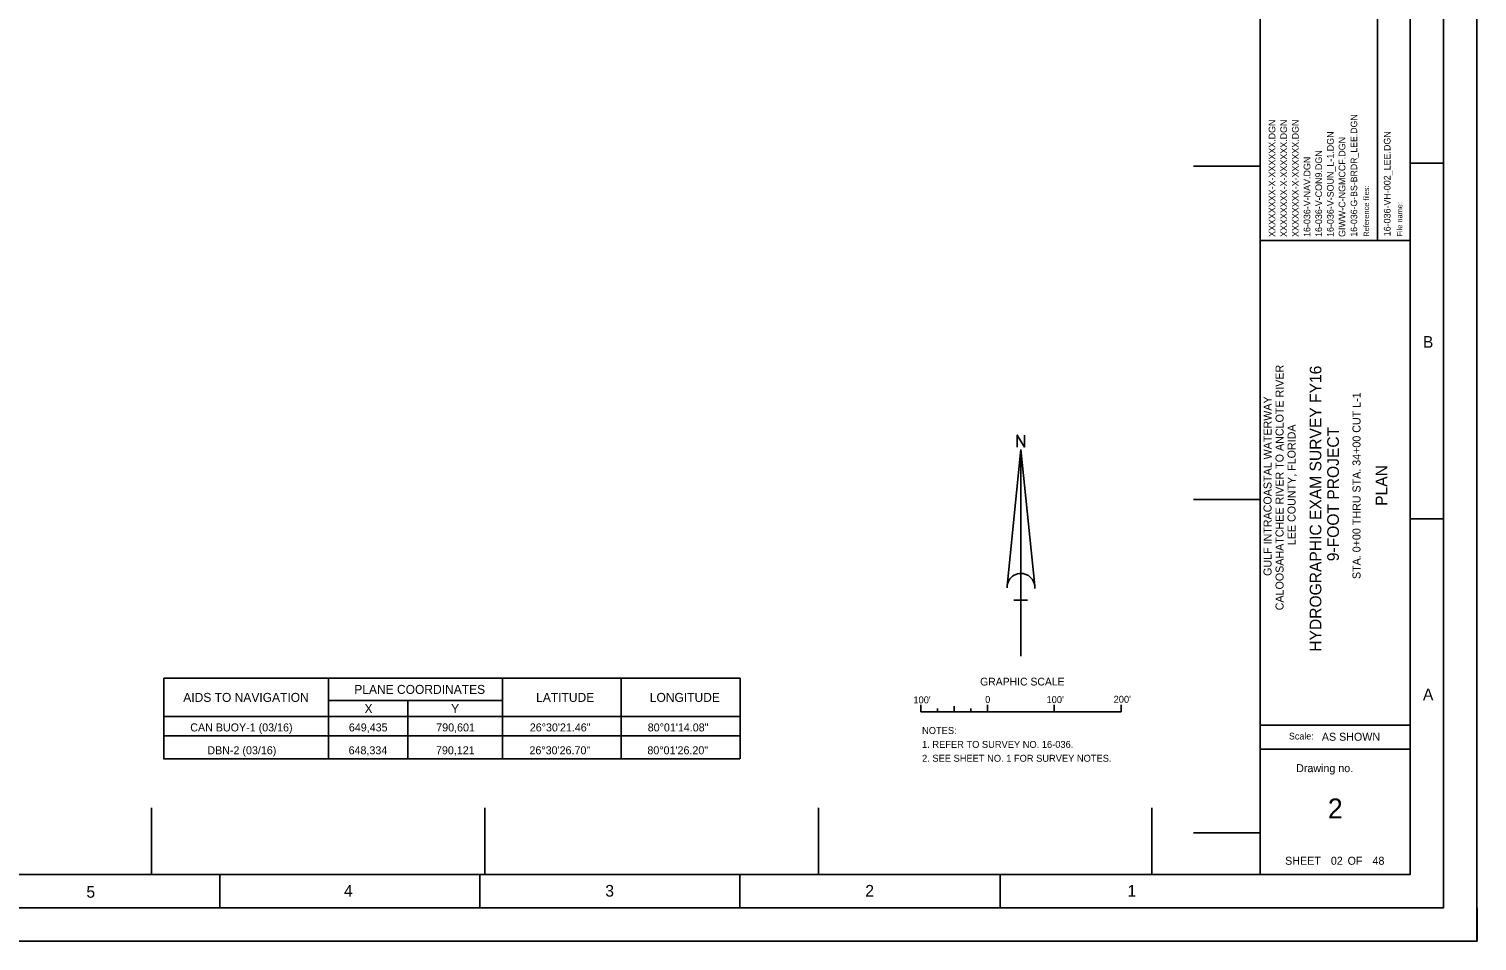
# Model space of a CAD drawing. Extents: x 647087 to 651487, y 788838 to 792238.
# Drawn here: x 649316 to 651487, y 788838 to 790206 of the extents above; entities that cross this region are included whole.
import ezdxf

# ---------------------------------------------------------------- set-up
doc = ezdxf.new("R2010")
doc.units = 0
for name, color, linetype in [('G-ANNO-NPLT', 7, 'Continuous'), ('G-ANNO-TEXT-DRWG', 7, 'Continuous'), ('G-ANNO-TEXT-PROJ', 7, 'Continuous'), ('G-ANNO-TEXT-TTLB', 7, 'Continuous'), ('G-ANNO-TTLB', 7, 'Continuous'), ('V-ANNO-NOTE', 7, 'Continuous'), ('V-ANNO-SCHD', 7, 'Continuous'), ('V-ANNO-SYMB', 7, 'Continuous'), ('V-TOPO-COOR-STAT', 7, 'Continuous')]:
    doc.layers.add(name, color=color, linetype=linetype)

msp = doc.modelspace()

# ---------------------------------------------------------------- linework, layer by layer
at = {"layer": 'G-ANNO-NPLT'}
msp.add_lwpolyline([(647087.3, 792237.8), (651487.3, 792237.8), (651487.3, 788837.9), (647087.3, 788837.9)], close=True, dxfattribs=at)
msp.add_lwpolyline([(651487.4, 788887.9), (651487.4, 788837.9), (651437.4, 788837.9)], dxfattribs=at)
at = {"layer": 'G-ANNO-TTLB'}
for p, q in [((651162.2, 792137.8), (651162.2, 788937.9)), ((651338, 790240), (651338, 789888.6)), ((651437.3, 790004.5), (651387.3, 790004.5)), ((651162.2, 789888.6), (651387.3, 789888.6)), ((651437.3, 789471.2), (651387.3, 789471.2)), ((651162.2, 789161.6), (651387.3, 789161.6)), ((651162.2, 789125.9), (651387.3, 789125.9)), ((649602.3, 788887.9), (649602.3, 788937.9)), ((649992.3, 788887.9), (649992.3, 788937.9)), ((650382.3, 788887.9), (650382.3, 788937.9)), ((650772.3, 788887.9), (650772.3, 788937.9))]:
    msp.add_line(p, q, dxfattribs=at)
for points in [[(647137.3, 788887.9), (651437.3, 788887.9), (651437.3, 792187.8), (647137.3, 792187.8)], [(651387.3, 792137.8), (647262.3, 792137.8), (647262.3, 788937.9), (651387.3, 788937.9)]]:
    msp.add_lwpolyline(points, close=True, dxfattribs=at)
at = {"layer": 'V-ANNO-NOTE'}
for p, q in [((650653.6, 789181.7), (650653.6, 789192.1)), ((650703.6, 789181.7), (650703.6, 789190.2)), ((650753.6, 789181.7), (650753.6, 789192.1)), ((650753.6, 789181.7), (650753.6, 789192.1)), ((650853.6, 789181.7), (650853.6, 789192.1)), ((650953.6, 789181.7), (650953.6, 789192.1)), ((650653.6, 789181.7), (650953.6, 789181.7)), ((650678.6, 789181.7), (650678.6, 789186.5)), ((650728.6, 789181.7), (650728.6, 789186.5)), ((650753.6, 789181.7), (650753.6, 789186.7))]:
    msp.add_line(p, q, dxfattribs=at)
at = {"layer": 'V-ANNO-SCHD'}
for p, q in [((649518.7, 789232.2), (650382.7, 789232.2)), ((649518.7, 789232.2), (649518.7, 789111.3)), ((649765.3, 789232.2), (649765.3, 789111.3)), ((650026, 789232.2), (650026, 789111.3)), ((650204.4, 789232.2), (650204.4, 789111.3)), ((650382.7, 789111.3), (650382.7, 789232.2)), ((649765.3, 789198.5), (650026, 789198.5)), ((649884.2, 789198.5), (649884.2, 789111.3)), ((649518.7, 789174.5), (650382.7, 789174.5)), ((649518.7, 789145.6), (650382.7, 789145.6)), ((649518.2, 789111.3), (650382.2, 789111.3))]:
    msp.add_line(p, q, dxfattribs=at)
at = {"layer": 'V-ANNO-SYMB'}
for p, q in [((650783, 789370.7), (650803.6, 789575.4)), ((650803.6, 789265.2), (650803.6, 789575.4)), ((650824.2, 789370.7), (650803.6, 789575.4)), ((650813.4, 789349), (650792.7, 789349))]:
    msp.add_line(p, q, dxfattribs=at)
msp.add_lwpolyline([(650797.9, 789578.8), (650797.9, 789596.9), (650809.1, 789578.8), (650809.1, 789596.9)], dxfattribs=at)
msp.add_arc((650803.6, 789368.6), 20.7, 355.2984, 182.0673, dxfattribs=at)
at = {"layer": 'V-TOPO-COOR-STAT'}
for p, q in [((651062.2, 790000), (651162.2, 790000)), ((651062.2, 789500), (651162.2, 789500)), ((649500, 788937.9), (649500, 789037.9)), ((650000, 788937.9), (650000, 789037.9)), ((650500, 788937.9), (650500, 789037.9)), ((651000, 788937.9), (651000, 789037.9)), ((651062.2, 789000), (651162.2, 789000))]:
    msp.add_line(p, q, dxfattribs=at)

# ---------------------------------------------------------------- texts
at = {"layer": 'G-ANNO-TEXT-DRWG'}
for s, height, p in [('XXXXXXXX-X-XXXXXX.DGN', 10, (651185, 789894)), ('XXXXXXXX-X-XXXXXX.DGN', 10, (651202.5, 789894)), ('XXXXXXXX-X-XXXXXX.DGN', 10, (651220, 789894)), ('16-036-V-SOUN_L-1.DGN', 10, (651272.5, 789894)), ('GIWW-C-NGMCCF.DGN', 10, (651290, 789894)), ('16-036-VH-002_LEE.DGN', 10, (651357.7, 789895)), ('16-036-V-NAV.DGN', 10, (651237.5, 789894)), ('16-036-V-CON9.DGN', 10, (651255, 789894)), ('STA. 0+00 THRU STA. 34+00 CUT L-1', 12, (651312.7, 789380.9)), ('PLAN', 17.5, (651352.8, 789490.6))]:
    msp.add_text(s, height=height, rotation=90, dxfattribs=at).set_placement(p)
for s, height, p in [('2', 30, (651263.7, 789021.7)), (' 02          48', 12, (651263.8, 788952.3))]:
    msp.add_text(s, height=height, dxfattribs=at).set_placement(p)
at = {"layer": 'G-ANNO-TEXT-PROJ'}
for s, height, p in [('16-036-G-BS-BRDR_LEE.DGN', 9.8, (651307.7, 789894.4)), ('CALOOSAHATCHEE RIVER TO ANCLOTE RIVER', 12, (651197.3, 789334)), ('HYDROGRAPHIC EXAM SURVEY FY16', 17.5, (651254, 789271.8)), ('GULF INTRACOASTAL WATERWAY', 12, (651179.3, 789385.6)), ('LEE COUNTY, FLORIDA', 12, (651215.3, 789431.7)), ('9-FOOT PROJECT', 17.5, (651280.3, 789407.6))]:
    msp.add_text(s, height=height, rotation=90, dxfattribs=at).set_placement(p)
at = {"layer": 'G-ANNO-TEXT-TTLB'}
for s, p in [('Reference files:', (651325.4, 789894.4)), ('File name:', (651375.4, 789894.7))]:
    msp.add_text(s, height=8, rotation=90, dxfattribs=at).set_placement(p)
for s, height, p in [('Scale:', 10, (651205.4, 789140.2)), ('AS SHOWN', 12, (651254.7, 789138.3)), ('Drawing no.', 12, (651216.1, 789091.2)), ('SHEET         OF', 12, (651199.7, 788952.3))]:
    msp.add_text(s, height=height, dxfattribs=at).set_placement(p)
at = {"layer": 'G-ANNO-TTLB'}
for s, p in [('B', (651406.3, 789727.8)), ('A', (651406.3, 789199.1)), ('5', (649402.4, 788902.9)), ('4', (649788.6, 788904.5)), ('3', (650180.4, 788904.5)), ('2', (650570.2, 788904.5)), ('1', (650963.4, 788904.5))]:
    msp.add_text(s, height=17.5, dxfattribs=at).set_placement(p)
at = {"layer": 'V-ANNO-NOTE'}
for s, height, p in [('GRAPHIC SCALE', 11.666, (650742.4, 789221.2)), ("100'", 10.42, (650642.3, 789194.4)), ('0', 10.4, (650749.9, 789195.1)), ("100'", 10.42, (650841.9, 789194.8)), ("200'", 10.42, (650942.5, 789195.3)), ('NOTES:', 10.42, (650655.3, 789148.5)), ('1. REFER TO SURVEY NO. 16-036.', 10.416, (650655.3, 789127.6)), ('2. SEE SHEET NO. 1 FOR SURVEY NOTES.', 10.416, (650655.3, 789106.8))]:
    msp.add_text(s, height=height, dxfattribs=at).set_placement(p)
at = {"layer": 'V-ANNO-SCHD'}
for s, height, p in [('AIDS TO NAVIGATION', 13.471, (649547.6, 789196.6)), ('PLANE COORDINATES', 13.471, (649804, 789208.6)), ('LATITUDE', 13.47, (650076.7, 789196.6)), ('LONGITUDE', 13.47, (650247.1, 789196.6)), ('X', 13.5, (649819.4, 789179.8)), ('Y', 13.5, (649949.2, 789179.8))]:
    msp.add_text(s, height=height, rotation=0.0001, dxfattribs=at).set_placement(p)
at = {"layer": 'V-ANNO-SYMB'}
for s, p in [('CAN BUOY-1 (03/16)', (649558.1, 789152.3)), ('649,435', (649795.9, 789152.3)), ('790,601', (649926.9, 789152.3)), ('26%%D30\'21.46"', (650067.2, 789152.3)), ('80%%D01\'14.08"', (650244, 789152.3)), ('DBN-2 (03/16)', (649583.7, 789118)), ('648,334', (649795.5, 789118)), ('790,121', (649926.5, 789118)), ('26%%D30\'26.70"', (650066.7, 789118)), ('80%%D01\'26.20"', (650243.5, 789118))]:
    msp.add_text(s, height=12, dxfattribs=at).set_placement(p)

doc.saveas('drawing.dxf')
